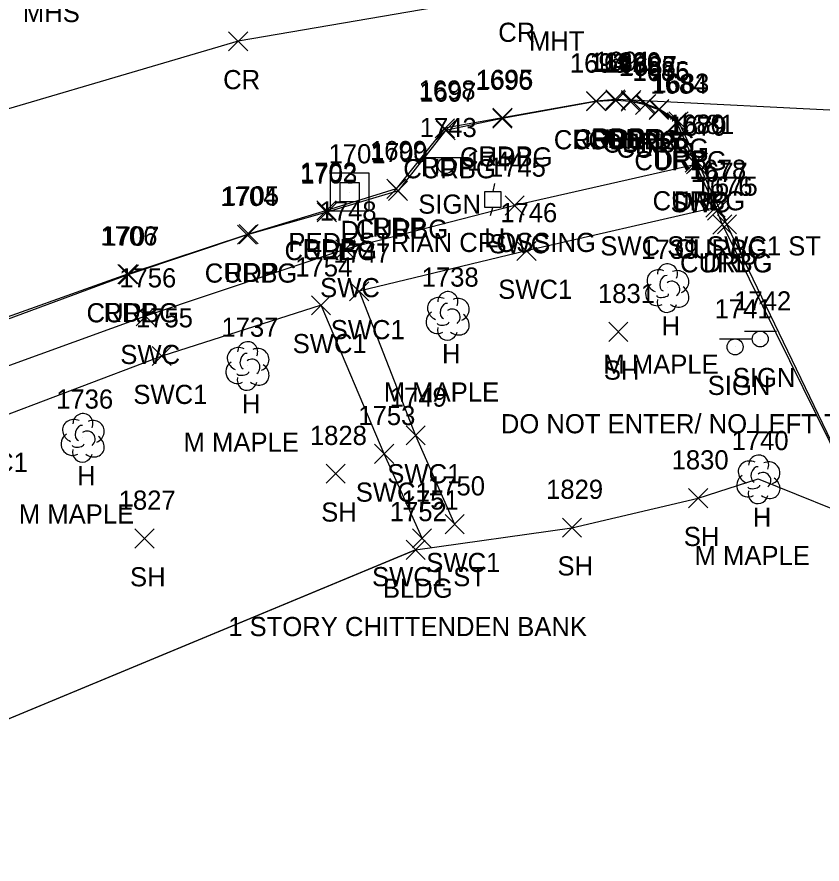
# Model space of a CAD drawing. Extents: x 1715662 to 1717487, y 887396 to 890004.
# Drawn here: x 1716199.7 to 1716283.7, y 888135.1 to 888223.5 of the extents above; entities that cross this region are included whole.
import ezdxf

# ---------------------------------------------------------------- set-up
doc = ezdxf.new("R2010")
doc.units = 0
for name, color, linetype in [('D_A', 7, 'Continuous'), ('D_I', 7, 'Continuous'), ('DS', 7, 'Continuous'), ('L_A', 7, 'Continuous'), ('L_C', 7, 'Continuous'), ('L_I', 7, 'Continuous'), ('L_TIC', 7, 'Continuous'), ('LBC', 7, 'Continuous'), ('LSOGP', 7, 'Continuous'), ('LTD', 7, 'Continuous'), ('P_A', 7, 'Continuous'), ('P_I', 7, 'Continuous'), ('P_TIC', 7, 'Continuous'), ('PET', 7, 'Continuous'), ('PRC', 7, 'Continuous'), ('R_A', 7, 'Continuous'), ('R_I', 7, 'Continuous'), ('R_TIC', 7, 'Continuous'), ('RC', 7, 'Continuous'), ('RDP', 7, 'Continuous'), ('RSW', 7, 'Continuous'), ('S_A', 7, 'Continuous'), ('S_C', 7, 'Continuous'), ('S_I', 7, 'Continuous'), ('SSGN', 7, 'Continuous'), ('U_A', 7, 'Continuous'), ('U_I', 7, 'Continuous'), ('ULP', 7, 'Continuous')]:
    doc.layers.add(name, color=color, linetype=linetype)

msp = doc.modelspace()

# ---------------------------------------------------------------- linework, layer by layer
at = {"layer": 'DS'}
for p, q in [((1716232.442, 888207.259), (1716236.441, 888207.259)), ((1716232.442, 888203.259), (1716232.442, 888207.259)), ((1716236.441, 888207.259), (1716236.441, 888203.259)), ((1716233.442, 888204.259), (1716233.442, 888206.259)), ((1716233.442, 888206.259), (1716235.442, 888206.259)), ((1716235.442, 888206.259), (1716235.442, 888204.259)), ((1716234.447, 888205.26), (1716234.447, 888205.26)), ((1716234.447, 888205.26), (1716234.447, 888205.26)), ((1716235.442, 888204.259), (1716233.442, 888204.259)), ((1716236.441, 888203.259), (1716232.442, 888203.259))]:
    msp.add_line(p, q, dxfattribs=at)
at = {"layer": 'L_TIC'}
for points in [[(1716261.486, 888189.671), (1716263.486, 888191.671)], [(1716263.486, 888189.671), (1716261.486, 888191.671)], [(1716231.982, 888174.855), (1716233.982, 888176.855)], [(1716233.982, 888174.855), (1716231.982, 888176.855)], [(1716269.822, 888172.304), (1716271.822, 888174.304)], [(1716271.822, 888172.304), (1716269.822, 888174.304)], [(1716256.644, 888169.229), (1716258.644, 888171.229)], [(1716258.644, 888169.229), (1716256.644, 888171.229)], [(1716212.027, 888168.096), (1716214.027, 888170.096)], [(1716214.027, 888168.096), (1716212.027, 888170.096)], [(1716240.324, 888166.9), (1716242.324, 888168.9)], [(1716242.324, 888166.9), (1716240.324, 888168.9)]]:
    msp.add_lwpolyline(points, dxfattribs=at)
at = {"layer": 'LBC'}
msp.add_lwpolyline([(1716241.324, 888167.9), (1716187.265, 888145.455), (1716180.213, 888142.314), (1716163.383, 888135.1)], dxfattribs=at)
at = {"layer": 'LSOGP'}
msp.add_lwpolyline([(1716187.262, 888145.453), (1716241.322, 888167.892), (1716257.642, 888170.222), (1716270.82, 888173.299), (1716277.08, 888175.313), (1716288.808, 888170.583)], dxfattribs=at)
at = {"layer": 'LTD'}
for p, q in [((1716267.569, 888195.286), (1716267.569, 888195.286)), ((1716267.569, 888195.286), (1716267.569, 888195.286)), ((1716244.649, 888192.386), (1716244.649, 888192.386)), ((1716244.649, 888192.386), (1716244.649, 888192.386)), ((1716223.751, 888187.156), (1716223.751, 888187.156)), ((1716223.751, 888187.156), (1716223.751, 888187.156)), ((1716206.556, 888179.651), (1716206.556, 888179.651)), ((1716206.556, 888179.651), (1716206.556, 888179.651)), ((1716277.082, 888175.318), (1716277.082, 888175.318)), ((1716277.082, 888175.318), (1716277.082, 888175.318))]:
    msp.add_line(p, q, dxfattribs=at)
for centre in [(1716267.616, 888196.72), (1716244.696, 888193.82), (1716223.798, 888188.59), (1716206.603, 888181.085), (1716277.129, 888176.752)]:
    msp.add_arc(centre, 1.047, 335.52715, 180.95627, dxfattribs=at)
for centre, major_axis, ratio, start_param, end_param in [((1716266.777, 888195.953), (1.21, -0.512), 0.895232, 1.570796, 4.712389), ((1716267.361, 888195.745), (-0.208, -0.792), 0.645439, 3.141593, 6.283185), ((1716268.611, 888195.87), (-1.141, -0.483), 0.949671, 1.570796, 4.712389), ((1716266.486, 888194.578), (0.584, -1.042), 0.959034, 3.141593, 6.283185), ((1716268.069, 888195.12), (-0.5, 0.667), 0.989748, 3.141593, 6.283185), ((1716267.111, 888194.536), (-0.625, -0.083), 0.423636, 0, 3.141593), ((1716268.569, 888194.453), (-1.09, 0.792), 0.841452, 1.570796, 4.712389), ((1716243.857, 888193.052), (1.21, -0.512), 0.895232, 1.570796, 4.712389), ((1716245.691, 888192.969), (-1.141, -0.483), 0.949671, 1.570796, 4.712389), ((1716267.569, 888193.786), (0.265, 1.061), 0.942809, 1.570796, 4.712389), ((1716244.441, 888192.844), (-0.208, -0.792), 0.645439, 3.141593, 6.283185), ((1716245.149, 888192.219), (-0.5, 0.667), 0.989748, 3.141593, 6.283185), ((1716243.566, 888191.677), (0.584, -1.042), 0.959034, 3.141593, 6.283185), ((1716245.649, 888191.553), (-1.09, 0.792), 0.841452, 1.570796, 4.712389), ((1716244.649, 888190.886), (0.265, 1.061), 0.942809, 1.570796, 4.712389), ((1716244.191, 888191.636), (-0.625, -0.083), 0.423636, 0, 3.141593), ((1716222.959, 888187.822), (1.21, -0.512), 0.895232, 1.570796, 4.712389), ((1716223.543, 888187.614), (-0.208, -0.792), 0.645439, 3.141593, 6.283185), ((1716224.793, 888187.739), (-1.141, -0.483), 0.949671, 1.570796, 4.712389), ((1716224.251, 888186.989), (-0.5, 0.667), 0.989748, 3.141593, 6.283185), ((1716222.668, 888186.447), (0.584, -1.042), 0.959034, 3.141593, 6.283185), ((1716224.751, 888186.323), (-1.09, 0.792), 0.841452, 1.570796, 4.712389), ((1716223.751, 888185.656), (0.265, 1.061), 0.942809, 1.570796, 4.712389), ((1716223.293, 888186.406), (-0.625, -0.083), 0.423636, 0, 3.141593), ((1716205.764, 888180.318), (1.21, -0.512), 0.895232, 1.570796, 4.712389), ((1716207.598, 888180.235), (-1.141, -0.483), 0.949671, 1.570796, 4.712389), ((1716206.348, 888180.11), (-0.208, -0.792), 0.645439, 3.141593, 6.283185), ((1716205.473, 888178.943), (0.584, -1.042), 0.959034, 3.141593, 6.283185), ((1716207.056, 888179.485), (-0.5, 0.667), 0.989748, 3.141593, 6.283185), ((1716207.556, 888178.818), (-1.09, 0.792), 0.841452, 1.570796, 4.712389), ((1716206.098, 888178.901), (-0.625, -0.083), 0.423636, 0, 3.141593), ((1716206.556, 888178.151), (0.265, 1.061), 0.942809, 1.570796, 4.712389), ((1716276.291, 888175.985), (1.21, -0.512), 0.895232, 1.570796, 4.712389), ((1716278.124, 888175.902), (-1.141, -0.483), 0.949671, 1.570796, 4.712389), ((1716276.874, 888175.776), (-0.208, -0.792), 0.645439, 3.141593, 6.283185), ((1716277.582, 888175.151), (-0.5, 0.667), 0.989748, 3.141593, 6.283185), ((1716275.999, 888174.61), (0.584, -1.042), 0.959034, 3.141593, 6.283185), ((1716278.083, 888174.485), (-1.09, 0.792), 0.841452, 1.570796, 4.712389), ((1716276.624, 888174.568), (-0.625, -0.083), 0.423636, 0, 3.141593), ((1716277.083, 888173.818), (0.265, 1.061), 0.942809, 1.570796, 4.712389)]:
    msp.add_ellipse(centre, major_axis=major_axis, ratio=ratio, start_param=start_param, end_param=end_param, dxfattribs=at)
at = {"layer": 'P_TIC'}
for points in [[(1716221.801, 888220.001), (1716223.801, 888222.001)], [(1716223.801, 888220.001), (1716221.801, 888222.001)], [(1716261.162, 888213.919), (1716263.162, 888215.919)], [(1716263.162, 888213.919), (1716261.162, 888215.919)], [(1716262.824, 888213.851), (1716264.824, 888215.851)], [(1716264.824, 888213.851), (1716262.824, 888215.851)], [(1716259.167, 888213.761), (1716261.167, 888215.761)], [(1716261.167, 888213.761), (1716259.167, 888215.761)], [(1716249.397, 888212.029), (1716251.397, 888214.029)], [(1716251.397, 888212.029), (1716249.397, 888214.029)], [(1716243.377, 888210.916), (1716245.377, 888212.916)], [(1716245.377, 888210.916), (1716243.377, 888212.916)], [(1716238.311, 888204.593), (1716240.311, 888206.593)], [(1716240.311, 888204.593), (1716238.311, 888206.593)], [(1716231.021, 888202.345), (1716233.021, 888204.345)], [(1716233.021, 888202.345), (1716231.021, 888204.345)], [(1716222.894, 888199.869), (1716224.894, 888201.869)], [(1716224.894, 888199.869), (1716222.894, 888201.869)], [(1716210.251, 888195.686), (1716212.251, 888197.686)], [(1716212.251, 888195.686), (1716210.251, 888197.686)]]:
    msp.add_lwpolyline(points, dxfattribs=at)
at = {"layer": 'PET'}
msp.add_lwpolyline([(1716420.853, 888214.165), (1716393.961, 888213.91), (1716351.519, 888213.452), (1716316.629, 888213.12), (1716287.306, 888213.672), (1716263.824, 888214.851), (1716262.162, 888214.919), (1716260.167, 888214.761), (1716250.397, 888213.029), (1716244.377, 888211.916), (1716239.311, 888205.593), (1716232.021, 888203.345), (1716223.894, 888200.869), (1716211.251, 888196.686), (1716194.262, 888190.63), (1716179.324, 888184.631), (1716135.646, 888166.652), (1716133.732, 888165.803), (1716132.447, 888164.774), (1716131.735, 888163.683), (1716109.75, 888154.128), (1716108.197, 888154.225), (1716106.259, 888154.029), (1716102.002, 888152.337)], dxfattribs=at)
at = {"layer": 'PRC'}
msp.add_lwpolyline([(1716552.725, 888226.159), (1716521.301, 888223.53), (1716490.76, 888225.549), (1716471.3, 888227.05), (1716451.951, 888228.645), (1716428.339, 888230.287), (1716394.243, 888231.396), (1716360.597, 888231.763), (1716326.714, 888231.11), (1716290.95, 888229.375), (1716251.515, 888225.942), (1716222.801, 888221.001), (1716188.274, 888210.848), (1716159.486, 888199.858), (1716131.412, 888188.248), (1716103.005, 888175.829)], dxfattribs=at)
at = {"layer": 'R_TIC'}
for points in [[(1716262.824, 888213.851), (1716264.824, 888215.851)], [(1716264.824, 888213.851), (1716262.824, 888215.851)], [(1716259.165, 888213.726), (1716261.165, 888215.726)], [(1716261.165, 888213.726), (1716259.165, 888215.726)], [(1716261.229, 888213.812), (1716263.229, 888215.812)], [(1716263.229, 888213.812), (1716261.229, 888215.812)], [(1716262.765, 888213.718), (1716264.765, 888215.718)], [(1716264.765, 888213.718), (1716262.765, 888215.718)], [(1716264.277, 888213.373), (1716266.277, 888215.373)], [(1716266.277, 888213.373), (1716264.277, 888215.373)], [(1716264.385, 888213.454), (1716266.385, 888215.454)], [(1716266.385, 888213.454), (1716264.385, 888215.454)], [(1716265.704, 888212.846), (1716267.704, 888214.846)], [(1716267.704, 888212.846), (1716265.704, 888214.846)], [(1716265.752, 888212.926), (1716267.752, 888214.926)], [(1716267.752, 888212.926), (1716265.752, 888214.926)], [(1716249.37, 888211.932), (1716251.37, 888213.932)], [(1716251.37, 888211.932), (1716249.37, 888213.932)], [(1716267.576, 888211.536), (1716269.576, 888213.536)], [(1716269.576, 888211.536), (1716267.576, 888213.536)], [(1716267.766, 888211.626), (1716269.766, 888213.626)], [(1716269.766, 888211.626), (1716267.766, 888213.626)], [(1716243.458, 888210.698), (1716245.458, 888212.698)], [(1716245.458, 888210.698), (1716243.458, 888212.698)], [(1716269.476, 888207.352), (1716271.476, 888209.352)], [(1716271.476, 888207.352), (1716269.476, 888209.352)], [(1716269.585, 888207.149), (1716271.585, 888209.149)], [(1716271.585, 888207.149), (1716269.585, 888209.149)], [(1716269.806, 888207.327), (1716271.806, 888209.327)], [(1716271.806, 888207.327), (1716269.806, 888209.327)], [(1716238.488, 888204.392), (1716240.488, 888206.392)], [(1716240.488, 888204.392), (1716238.488, 888206.392)], [(1716250.67, 888202.865), (1716252.67, 888204.865)], [(1716252.67, 888202.865), (1716250.67, 888204.865)], [(1716271.626, 888202.641), (1716273.626, 888204.641)], [(1716273.626, 888202.641), (1716271.626, 888204.641)], [(1716271.626, 888202.641), (1716273.626, 888204.641)], [(1716273.626, 888202.641), (1716271.626, 888204.641)], [(1716231.059, 888202.154), (1716233.059, 888204.154)], [(1716233.059, 888202.154), (1716231.059, 888204.154)], [(1716271.78, 888202.323), (1716273.78, 888204.323)], [(1716273.78, 888202.323), (1716271.78, 888204.323)], [(1716272.341, 888200.87), (1716274.341, 888202.87)], [(1716274.341, 888200.87), (1716272.341, 888202.87)], [(1716272.341, 888200.87), (1716274.341, 888202.87)], [(1716274.341, 888200.87), (1716272.341, 888202.87)], [(1716272.825, 888200.886), (1716274.825, 888202.886)], [(1716274.825, 888200.886), (1716272.825, 888202.886)], [(1716222.732, 888199.807), (1716224.732, 888201.807)], [(1716224.732, 888199.807), (1716222.732, 888201.807)], [(1716232.992, 888198.285), (1716234.992, 888200.285)], [(1716234.992, 888198.285), (1716232.992, 888200.285)], [(1716251.904, 888198.113), (1716253.904, 888200.113)], [(1716253.904, 888198.113), (1716251.904, 888200.113)], [(1716210.394, 888195.658), (1716212.394, 888197.658)], [(1716212.394, 888195.658), (1716210.394, 888197.658)], [(1716234.427, 888193.899), (1716236.427, 888195.899)], [(1716236.427, 888193.899), (1716234.427, 888195.899)], [(1716230.456, 888192.442), (1716232.456, 888194.442)], [(1716232.456, 888192.442), (1716230.456, 888194.442)], [(1716212.14, 888191.306), (1716214.14, 888193.306)], [(1716214.14, 888191.306), (1716212.14, 888193.306)], [(1716213.824, 888187.137), (1716215.824, 888189.137)], [(1716215.824, 888187.137), (1716213.824, 888189.137)], [(1716240.329, 888178.856), (1716242.329, 888180.856)], [(1716242.329, 888178.856), (1716240.329, 888180.856)], [(1716237.04, 888176.933), (1716239.04, 888178.933)], [(1716239.04, 888176.933), (1716237.04, 888178.933)], [(1716244.398, 888169.588), (1716246.398, 888171.588)], [(1716246.398, 888169.588), (1716244.398, 888171.588)], [(1716240.997, 888168.11), (1716242.997, 888170.11)], [(1716242.997, 888168.11), (1716240.997, 888170.11)]]:
    msp.add_lwpolyline(points, dxfattribs=at)
at = {"layer": 'RC'}
for points in [[(1716270.476, 888208.352), (1716268.576, 888212.536), (1716266.704, 888213.846), (1716265.277, 888214.373), (1716263.765, 888214.718), (1716262.229, 888214.812), (1716260.165, 888214.726), (1716250.37, 888212.932), (1716244.458, 888211.698), (1716239.488, 888205.392), (1716232.059, 888203.154), (1716223.732, 888200.807), (1716211.394, 888196.658), (1716194.256, 888190.314), (1716179.271, 888184.533), (1716135.621, 888166.462), (1716133.741, 888165.72), (1716132.485, 888164.669), (1716131.864, 888163.647), (1716131.26, 888162.31), (1716130.838, 888160.611)], [(1716273.341, 888201.87), (1716272.78, 888203.323)], [(1716288.811, 888170.587), (1716273.341, 888201.87)]]:
    msp.add_lwpolyline(points, dxfattribs=at)
at = {"layer": 'RDP'}
msp.add_lwpolyline([(1716288.839, 888170.666), (1716273.825, 888201.886), (1716270.806, 888208.327), (1716268.766, 888212.626), (1716266.752, 888213.926), (1716265.385, 888214.454), (1716263.824, 888214.851)], dxfattribs=at)
at = {"layer": 'RSW'}
for points in [[(1716272.626, 888203.641), (1716270.585, 888208.149), (1716251.67, 888203.865), (1716233.992, 888199.285), (1716213.14, 888192.306), (1716194.587, 888185.593), (1716170.145, 888175.903), (1716142.849, 888164.263), (1716131.693, 888159.689), (1716133.515, 888155.156)], [(1716272.626, 888203.641), (1716252.904, 888199.113), (1716235.427, 888194.899), (1716241.329, 888179.856), (1716245.398, 888170.588)], [(1716241.997, 888169.11), (1716238.04, 888177.933), (1716231.456, 888193.442), (1716214.824, 888188.137), (1716196.083, 888181.043), (1716175.818, 888172.935), (1716187.265, 888145.455)]]:
    msp.add_lwpolyline(points, dxfattribs=at)
at = {"layer": 'SSGN'}
for p, q in [((1716242.819, 888208.857), (1716246.153, 888208.857)), ((1716244.466, 888208.023), (1716244.466, 888208.023)), ((1716275.642, 888190.752), (1716278.975, 888190.752)), ((1716273.026, 888189.929), (1716276.36, 888189.929)), ((1716277.289, 888189.919), (1716277.289, 888189.919)), ((1716274.673, 888189.096), (1716274.673, 888189.096))]:
    msp.add_line(p, q, dxfattribs=at)
for centre in [(1716244.466, 888208.023), (1716277.289, 888189.919), (1716274.673, 888189.096)]:
    msp.add_circle(centre, 0.833, dxfattribs=at)
at = {"layer": 'ULP'}
for p, q in [((1716249.545, 888206.151), (1716249.378, 888205.318)), ((1716248.545, 888203.651), (1716248.545, 888205.318)), ((1716248.545, 888205.318), (1716250.212, 888205.318)), ((1716250.212, 888205.318), (1716250.212, 888203.651)), ((1716249.378, 888204.484), (1716249.378, 888204.484)), ((1716250.212, 888203.651), (1716248.545, 888203.651)), ((1716249.128, 888202.818), (1716249.378, 888203.651))]:
    msp.add_line(p, q, dxfattribs=at)

# ---------------------------------------------------------------- texts
at = {"layer": 'D_A'}
msp.add_text('DI', height=2, dxfattribs=at).set_placement((1716233.502, 888200.26))
at = {"layer": 'D_I'}
msp.add_text('1701', height=2, dxfattribs=at).set_placement((1716232.242, 888208.26))
at = {"layer": 'L_A'}
for s, p in [('H', (1716267.002, 888190.286)), ('H', (1716244.082, 888187.386)), ('SH', (1716260.974, 888185.671)), ('H', (1716223.184, 888182.156)), ('H', (1716205.989, 888174.651)), ('SH', (1716231.47, 888170.855)), ('H', (1716276.515, 888170.318)), ('SH', (1716269.311, 888168.304)), ('SH', (1716256.132, 888165.229)), ('SH', (1716211.515, 888164.096)), ('BLDG', (1716237.915, 888162.9))]:
    msp.add_text(s, height=2, dxfattribs=at).set_placement(p)
at = {"layer": 'L_C'}
for s, p in [('M MAPLE', (1716260.924, 888186.286)), ('M MAPLE', (1716238.003, 888183.386)), ('M MAPLE', (1716217.105, 888178.156)), ('M MAPLE', (1716199.91, 888170.651)), ('M MAPLE', (1716270.437, 888166.318)), ('1 STORY CHITTENDEN BANK', (1716221.765, 888158.9))]:
    msp.add_text(s, height=2, dxfattribs=at).set_placement(p)
at = {"layer": 'L_I'}
for s, p in [('1739', (1716264.868, 888198.286)), ('1738', (1716241.956, 888195.386)), ('1831', (1716260.36, 888193.671)), ('1737', (1716221.058, 888190.156)), ('1736', (1716203.808, 888182.651)), ('1828', (1716230.289, 888178.855)), ('1740', (1716274.303, 888178.318)), ('1830', (1716268.043, 888176.304)), ('1829', (1716254.943, 888173.229)), ('1827', (1716210.334, 888172.096)), ('1752', (1716238.631, 888170.9))]:
    msp.add_text(s, height=2, dxfattribs=at).set_placement(p)
at = {"layer": 'P_A'}
for s, p in [('CR', (1716249.948, 888220.942)), ('CR', (1716221.234, 888216.001)), ('RDP', (1716257.655, 888209.761)), ('RDP', (1716259.651, 888209.919)), ('RDP', (1716261.312, 888209.851)), ('RDP', (1716247.885, 888208.029)), ('RDP', (1716241.865, 888206.916)), ('RDP', (1716236.799, 888200.593)), ('RDP', (1716229.509, 888198.345)), ('RDP', (1716221.382, 888195.869)), ('RDP', (1716208.74, 888191.686))]:
    msp.add_text(s, height=2, dxfattribs=at).set_placement(p)
at = {"layer": 'P_I'}
for s, p in [('1694', (1716257.427, 888217.761)), ('1691', (1716259.989, 888217.919)), ('1690', (1716260.997, 888217.851)), ('1695', (1716247.657, 888216.029)), ('1698', (1716241.637, 888214.916)), ('1699', (1716236.563, 888208.593)), ('1702', (1716229.249, 888206.345)), ('1705', (1716221.123, 888203.869)), ('1706', (1716208.425, 888199.686))]:
    msp.add_text(s, height=2, dxfattribs=at).set_placement(p)
at = {"layer": 'R_A'}
for s, p in [('CURBG', (1716255.748, 888209.726)), ('CURBG', (1716257.811, 888209.812)), ('CURBG', (1716259.347, 888209.718)), ('DRP', (1716261.312, 888209.851)), ('DRP', (1716262.873, 888209.454)), ('CURBG', (1716260.859, 888209.373)), ('CURBG', (1716262.287, 888208.846)), ('DRP', (1716264.241, 888208.926)), ('CURBG', (1716245.952, 888207.932)), ('CURBG', (1716264.158, 888207.536)), ('DRP', (1716266.254, 888207.626)), ('CURBG', (1716240.041, 888206.698)), ('CURBG', (1716266.059, 888203.352)), ('DRP', (1716268.294, 888203.327)), ('SWC', (1716267.947, 888203.149)), ('CURBG', (1716235.071, 888200.392)), ('SWC', (1716249.032, 888198.865)), ('CURBG', (1716227.642, 888198.154)), ('SWC ST SWC1 ST', (1716260.603, 888198.641)), ('SWC ST SWC1 ST', (1716260.603, 888198.641)), ('CURBG', (1716268.363, 888198.323)), ('CURBC', (1716268.924, 888196.87)), ('CURBG', (1716268.924, 888196.87)), ('DRP', (1716271.313, 888196.886)), ('CURBG', (1716219.315, 888195.807)), ('SWC', (1716231.354, 888194.285)), ('SWC1', (1716249.944, 888194.113)), ('CURBG', (1716206.977, 888191.658)), ('SWC1', (1716232.466, 888189.899)), ('SWC1', (1716228.495, 888188.442)), ('SWC', (1716210.502, 888187.306)), ('SWC1', (1716211.863, 888183.137)), ('SWC1', (1716193.122, 888176.043)), ('SWC1', (1716238.368, 888174.856)), ('SWC1', (1716235.08, 888172.933)), ('SWC1', (1716242.438, 888165.588)), ('SWC1 ST', (1716236.776, 888164.11))]:
    msp.add_text(s, height=2, dxfattribs=at).set_placement(p)
at = {"layer": 'R_I'}
for s, p in [('1693', (1716257.425, 888217.726)), ('1692', (1716259.489, 888217.812)), ('1690', (1716260.997, 888217.851)), ('1689', (1716261.017, 888217.718)), ('1688', (1716262.536, 888217.373)), ('1687', (1716262.645, 888217.454)), ('1686', (1716263.957, 888216.926)), ('1685', (1716263.964, 888216.846)), ('1696', (1716247.574, 888215.932)), ('1683', (1716266.025, 888215.626)), ('1697', (1716241.718, 888214.698)), ('1684', (1716265.836, 888215.536)), ('1680', (1716267.65, 888211.352)), ('1681', (1716268.632, 888211.327)), ('1679', (1716267.837, 888211.149)), ('1700', (1716236.63, 888208.392)), ('1745', (1716248.977, 888206.865)), ('1703', (1716229.287, 888206.154)), ('1678', (1716269.886, 888206.641)), ('1678', (1716269.886, 888206.641)), ('1677', (1716270.04, 888206.323)), ('1676', (1716270.546, 888204.87)), ('1676', (1716270.546, 888204.87)), ('1675', (1716271.085, 888204.886)), ('1704', (1716220.961, 888203.807)), ('1748', (1716231.299, 888202.285)), ('1746', (1716250.156, 888202.113)), ('1707', (1716208.622, 888199.658)), ('1747', (1716232.734, 888197.899)), ('1754', (1716228.763, 888196.442)), ('1756', (1716210.392, 888195.306)), ('1755', (1716212.131, 888191.137)), ('1749', (1716238.628, 888182.856)), ('1753', (1716235.347, 888180.933)), ('1750', (1716242.619, 888173.588)), ('1751', (1716239.871, 888172.11))]:
    msp.add_text(s, height=2, dxfattribs=at).set_placement(p)
at = {"layer": 'S_A'}
for p in [(1716241.604, 888203.003), (1716274.427, 888184.898), (1716271.811, 888184.076)]:
    msp.add_text('SIGN', height=2, dxfattribs=at).set_placement(p)
at = {"layer": 'S_C'}
for s, p in [('PEDESTRIAN CROSSING', (1716228.045, 888199.003)), ('DO NOT ENTER/ NO LEFT TURN', (1716250.22, 888180.076))]:
    msp.add_text(s, height=2, dxfattribs=at).set_placement(p)
at = {"layer": 'S_I'}
for s, p in [('1743', (1716241.754, 888211.003)), ('1742', (1716274.576, 888192.898)), ('1741', (1716272.528, 888192.076))]:
    msp.add_text(s, height=2, dxfattribs=at).set_placement(p)
at = {"layer": 'U_A'}
for s, p in [('MHS', (1716200.332, 888223.007)), ('MHT', (1716253.156, 888220.04)), ('LI', (1716248.481, 888199.484))]:
    msp.add_text(s, height=2, dxfattribs=at).set_placement(p)
at = {"layer": 'U_I'}
msp.add_text('1744', height=2, dxfattribs=at).set_placement((1716246.685, 888207.484))

doc.saveas('drawing.dxf')
